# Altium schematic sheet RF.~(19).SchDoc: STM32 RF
size A4; Date: Not used; ApprovedBy: Not used; CheckedBy: Not used; Author: Not used; CompanyName: STMicroelectronics; DrawnBy: Not used; Engineer: Not used; Organization: Not used; Address1: Not used; Address2: Not used; Address3: Not used; Address4: Not used; DocumentNumber: Not used; Revision: Not used; SheetNumber: 5; SheetTotal: 5
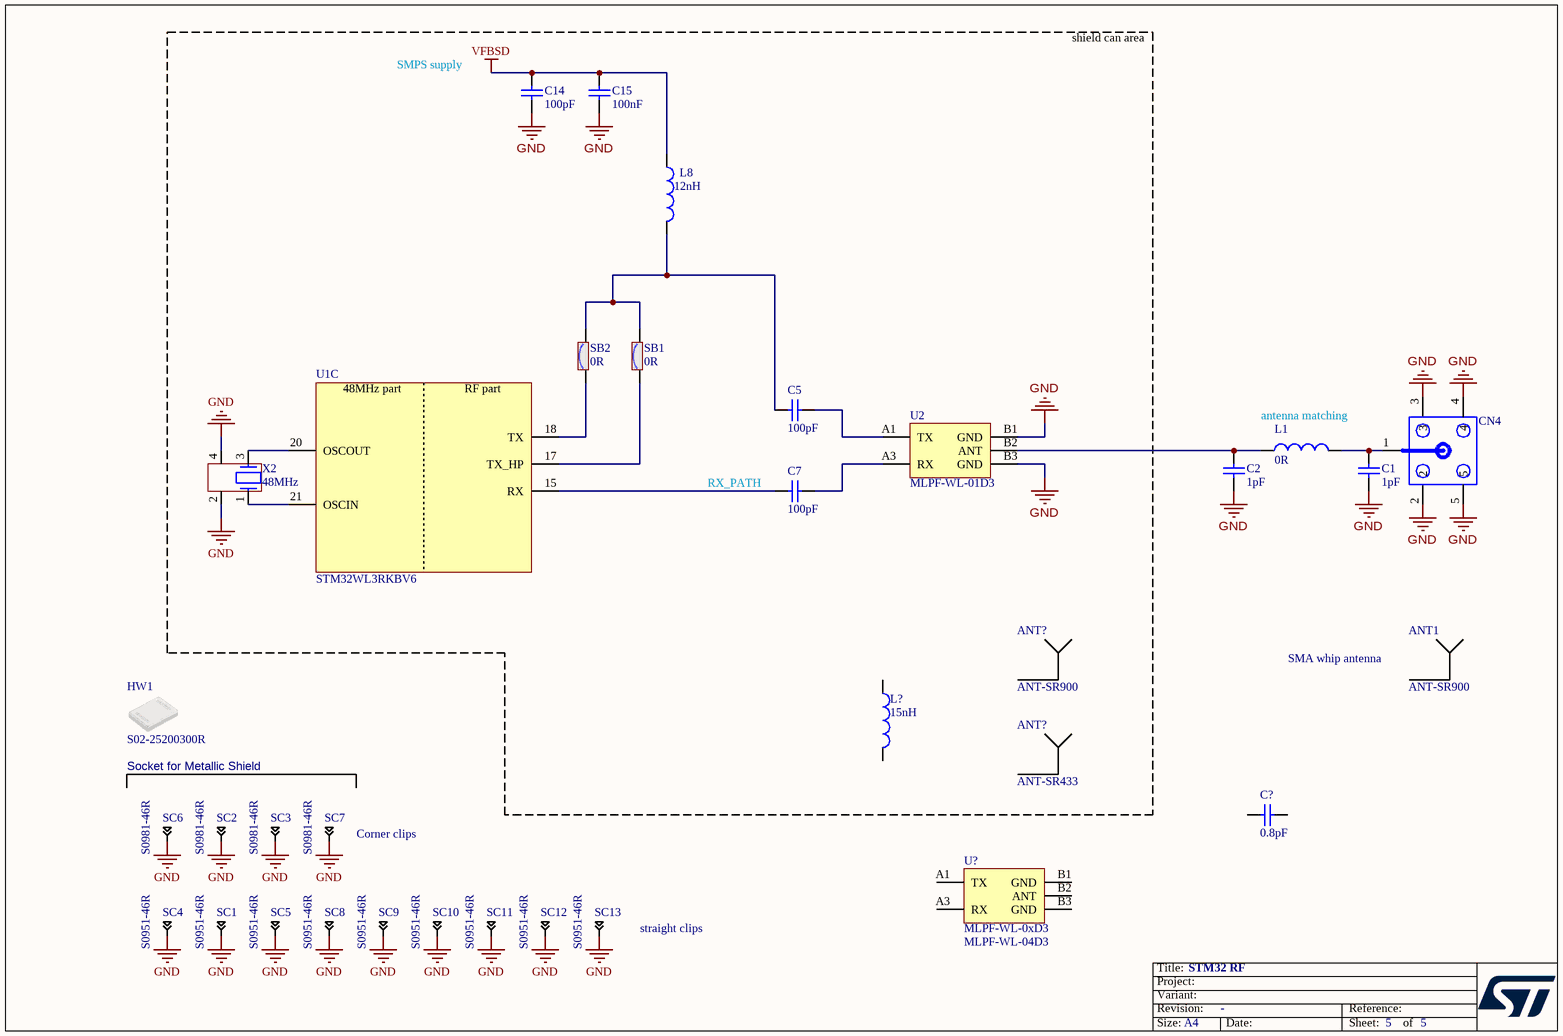
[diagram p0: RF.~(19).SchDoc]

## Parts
(Parts that share a designator on the sheet are numbered #1, #2 ... from top to bottom, then left to right.)
ANT1  value ANT-SR900  (hidden comment: ANT)  (mechanical)
ANT?#1  value ANT-SR900  (hidden comment: ANT)
ANT?#2  value ANT-SR433  (hidden comment: ANT)
C1  value 1pF  [C0402]  (hidden comment: Capacitor)
C2  value 1pF  [C0402]  (hidden comment: Capacitor)
C5  value 100pF  [C0402]  (hidden comment: Capacitor)
C7  value 100pF  [C0402]  (hidden comment: Capacitor)
C14  value 100pF  [C0402]  (hidden comment: Capacitor)
C15  value 100nF  [C0402]  (hidden comment: Capacitor)
C?  value 0.8pF  [C0402]  (hidden comment: Capacitor)
CN4  mmcx  [CON_SMA-RF_CINCH_142-0701-851]  (value not drawn)
HW1  value S02-25200300R  [SHIELD_HARWIN_S02-25200300_20X25_H3]  (hidden comment: S02-20150300)
L1  value 0R  [L0402]  (hidden comment: Inductor)
L8  value 12nH  [IND_0402_MURATA_LQW15ANXXXX00_H0P5]  (hidden comment: Inductor)
L?  value 15nH  [IND_0402_MURATA_LQW15ANXXXX00_H0P5]  (hidden comment: Inductor)
SB1  value 0R  [SOLDER-BRIDGE_R0201_0R]  (hidden comment: SB_ON)
SB2  value 0R  [SOLDER-BRIDGE_R0201_0R]  (hidden comment: SB_ON)
SC1  value S0951-46R  [CLIP_HARWIN_S0951-46R]  (hidden comment: Shield-clip_S0951-46R)
SC2  value S0981-46R  [CLIP_HARWIN_S0981-46R]  (hidden comment: Shield-clip_S0951-46R)
SC3  value S0981-46R  [CLIP_HARWIN_S0981-46R]  (hidden comment: Shield-clip_S0951-46R)
SC4  value S0951-46R  [CLIP_HARWIN_S0951-46R]  (hidden comment: Shield-clip_S0951-46R)
SC5  value S0951-46R  [CLIP_HARWIN_S0951-46R]  (hidden comment: Shield-clip_S0951-46R)
SC6  value S0981-46R  [CLIP_HARWIN_S0981-46R]  (hidden comment: Shield-clip_S0951-46R)
SC7  value S0981-46R  [CLIP_HARWIN_S0981-46R]  (hidden comment: Shield-clip_S0951-46R)
SC8  value S0951-46R  [CLIP_HARWIN_S0951-46R]  (hidden comment: Shield-clip_S0951-46R)
SC9  value S0951-46R  [CLIP_HARWIN_S0951-46R]  (hidden comment: Shield-clip_S0951-46R)
SC10  value S0951-46R  [CLIP_HARWIN_S0951-46R]  (hidden comment: Shield-clip_S0951-46R)
SC11  value S0951-46R  [CLIP_HARWIN_S0951-46R]  (hidden comment: Shield-clip_S0951-46R)
SC12  value S0951-46R  [CLIP_HARWIN_S0951-46R]  (hidden comment: Shield-clip_S0951-46R)
SC13  value S0951-46R  [CLIP_HARWIN_S0951-46R]  (hidden comment: Shield-clip_S0951-46R)
U1  value STM32WL3RKBV6  [ICC_VFQFPN32-EPAD_5X5_P050]  (hidden comment: IC_STM32WL3R)  (part C of 3)
U2  value MLPF-WL-01D3  [ICC_CSPG5_1P5X1P9_P060]  (hidden comment: MLPF-WL-0xD3)
U?  MLPF-WL-0xD3  value MLPF-WL-04D3  [ICC_CSPG5_1P5X1P9_P060]
X2  value 48MHz  [CRY_NX1612SA_4P]  (hidden comment: XTAL_4_PINS)

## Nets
GND: C1.1 C2.1 C14.2 C15.1 CN4.2 CN4.3 CN4.4 CN4.5 SC1.1 SC2.1 SC3.1 SC4.1 SC5.1 SC6.1 SC7.1 SC8.1 SC9.1 SC10.1 SC11.1 SC12.1 SC13.1 U2.B1(GND) U2.B3(GND) X2.2 X2.4
VFBSD: C14.1 C15.2 L8.1
NetC1_2: C1.2 CN4.1 L1.2
NetC2_2: C2.2 L1.1 U2.B2(ANT)
NetC5_1: C5.1 U2.A1(TX)
NetC5_2: C5.2 L8.2 SB1.2 SB2.2
NetC7_1: C7.1 U1.15(RX)
NetC7_2: C7.2 U2.A3(RX)
NetSB1_1: SB1.1 U1.17(TX_HP)
NetSB2_1: SB2.1 U1.18(TX)
NetU1_20: U1.20(OSCOUT) X2.3
NetU1_21: U1.21(OSCIN) X2.1

Not connected (* = marked no-connect by the designer): C? 1 2; L? 1 2; U? A1(TX) A3(RX) B1(GND) B2(ANT) B3(GND)

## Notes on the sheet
- shield can area
- SMPS supply
- antenna matching
- (near C7) RX_PATH
- SMA whip antenna
- Socket for Metallic Shield
- (near SC7) Corner clips
- (near SC13) straight clips

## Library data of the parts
ANT1 ANT?#1 = MCD-03598: Antenna, 868MHz To 915MHz, Compressed whip, SMA right angle; Part_Type: Misc; Part_Preference: Recommended; Manufacturer: LPRS; Component_Country_Of_Origin: China°; ShowFields: YES; ID: 5714
ANT?#2 = MCD-03599: Antenna, 420MHz To 470MHz, Compressed whip, SMA right angle; Part_Type: Misc; Part_Preference: Recommended; Manufacturer: LPRS; Order_Code_RS: 172-2307; Component_Country_Of_Origin: China°; ShowFields: YES; ID: 5715
C1 C2 = MCD-01600: Capacitor, MLCC, 1pF, 50V, NPO, +/-0.1pF, 0402, T=0.5mm; Part_Preference: Recommended; Manufacturer: YAGEO; Manufacturer_Part_Number: CC0402BRNPO9BN1R0; Component_Country_Of_Origin: China; ShowFields: YES; ID: 3700
C5 C14 = MCD-03446: Capacitor, MLCC, 100pF, 50V, COG, 1%, 0402, T=0.5mm; Part_Preference: Recommended; Manufacturer: MURATA; Manufacturer_Part_Number: GCM1555C1H101FA16; Order_Code_RS: 247-7780; ShowFields: YES; ID: 5562
C7 = MCD-03446: Capacitor, MLCC, 100pF, 50V, COG, +/-1%, 0402, T=0.5mm; Part_Preference: Recommended; Manufacturer: MURATA; Manufacturer_Part_Number: GCM1555C1H101FA16; Order_Code_RS: 247-7780; Component_Country_Of_Origin: China,  Japan, Philippines, Singapore; ShowFields: YES; ID: 5562
C15 = MCD-03442: Capacitor, MLCC, 100nF, ±10%, X7R, 25V, 0402, T=0.5mm; Part_Preference: Recommended; Manufacturer: MURATA; Manufacturer_Part_Number: GRM155R71E104KE14D; Order_Code_RS: 247-8011; ShowFields: YES; ID: 5558
C? = MCD-03643: Capacitor, MLCC, 0.8pF, 50V, C0G/NP0, +/-0.1pF, 0402, T=0.5mm; Part_Preference: Recommended; Manufacturer: MURATA; Manufacturer_Part_Number: GJM1555C1HR80BB01; Order_Code_RS: 114-0369; Component_Country_Of_Origin: Japan, Singapore; ShowFields: YES; ID: 5759
CN4 = MCD-02072: Jack_SMA, VR, PCB edge, 50R, T=7.92mm; Part_Type: Connector; Part_Preference: Recommended; Manufacturer: CINCH; Manufacturer_Part_Number: 142-0701-851; Order_Code_RS: 885-7532; Component_Country_Of_Origin: United States; ShowFields: YES; ID: 4172
HW1 = MCD-03503: RFI shield CAN, 25x20x3mm; Part_Type: Misc; Part_Preference: Recommended; Manufacturer: HARWIN; Order_Code_RS: 247-9196; Component_Country_Of_Origin: UK°; ShowFields: YES; ID: 5619
L1 = MCD-01937: Resistor, 0R, 0402, +/-5%, 1/16W; Part_Preference: Recommended; Manufacturer: YAGEO; Manufacturer_Part_Number: RC0402JR-070RL; Order_Code_RS: 618-5804; Component_Country_Of_Origin: China; ShowFields: YES; ID: 4037
L8 = MCD-03456: Inductor, 12nH, +/-2%, 500mA, 0R14, 0402, T=0.5mm; Part_Preference: Recommended; Manufacturer: MURATA; Manufacturer_Part_Number: LQW15AN12NG00D; Order_Code_RS: 2840126RL; ShowFields: YES; ID: 5572; Component_Country_Of_Origin: Japan, Malaysia
L? = MCD-01766: Inductor, 15nH, +/-2%, Itemp=460mA max, 0R16, 0402, T= 0.6mm, Qmin=30; Part_Preference: Recommended; Manufacturer: MURATA; Manufacturer_Part_Number: LQW15AN15NG00; Order_Code_RS: 187-3568; Component_Country_Of_Origin: Japan°°; ShowFields: YES; ID: 3866
SB1 SB2 = MCD-03219: Solder Bridge ON, 0R, 0201, 1/20W; Part_Type: Misc; Part_Preference: Recommended; Manufacturer: YAGEO; Manufacturer_Part_Number: RC0201JR-070RL; Order_Code_RS: 198-7623; Component_Country_Of_Origin: China; ShowFields: YES; ID: 5335
SC1 SC4 SC5 SC8 = MCD-01587: shield clip Harwin S0951-46R to fix RF shielded cavity; Part_Type: Misc; Part_Preference: Recommended; Component_Country_Of_Origin: South Korea
SC2 SC3 SC6 SC7 = MCD-02164: shield clip Harwin S0981-46R to fix RF shielded cavity - SMT RFI Shield Clip, Corner (T+R); Part_Type: Misc; Part_Preference: Recommended; Order_Code_RS: 161-3702; Component_Country_Of_Origin: South Korea; ShowFields: YES; ID: 4264
SC9-SC13 = MCD-01587: RFI shield clip mini TIN SMD; Part_Type: Mechanical; Part_Preference: Recommended; Manufacturer: HARWIN; Component_Country_Of_Origin: South Korea; ShowFields: YES; ID: 3687
U1 = MCD-04431: MCU, ARM Cortex-M0 32-bit, 128KB Flash, 16KB SRAM, With Crypto; Part_Type: IC; Part_Preference: Recommended; Manufacturer: STMICROELECTRONICS; ShowFields: YES; ID: 6547
U2 = MCD-03962: IC, 862 To 928MHz,16dBm, 4L PCB, IPD for STM32WL3; Part_Preference: Not recommended; Manufacturer: STMICROELECTRONICS; ShowFields: YES; ID: 6078; Component_Country_Of_Origin: Unknown
U? = MCD-03964: IC, 412 To 479MHz, 16dBm, 4L PCB, IPD for STM32WL3; Part_Preference: Not recommended; Manufacturer: STMICROELECTRONICS; Component_Country_Of_Origin: Unknown; ShowFields: YES; ID: 6080
X2 = MCD-03559: Crystal, 48MHz, 8pF, +/-10 ppm, 22R, 1.6x1.2mm; Part_Type: Crystal_Osc; Part_Preference: Recommended; Manufacturer: NDK; Manufacturer_Part_Number: NX1612SA-48.000 MHz-EXS00A-CS12140; ShowFields: YES; ID: 5675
